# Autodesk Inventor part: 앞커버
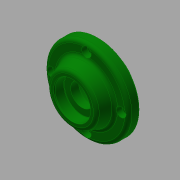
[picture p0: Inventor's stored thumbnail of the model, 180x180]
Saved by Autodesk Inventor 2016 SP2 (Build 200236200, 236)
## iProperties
Created: 2017-08
Part Number: 앞커버
Material: 알루미늄 6061
Document SubType Name: Modeling
Designer: mduedu
Density: 1 g/cm^3
Appearance: 진녹색
Author: mduedu
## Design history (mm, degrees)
sketch "스케치1"
  geometry: C1 r 35 at (0, 0); 1 further point
  constraints: 1 centre point, 1 coincident
  dimensions: "d0" = 70 diameter of C1
extrude "돌출1" new body sketch "스케치1" distance "d1" = 10; taper "d2" = 0 deg
sketch "스케치2"
  geometry: C1 r 24 at (0, 0); 1 further point
  constraints: 1 centre point, 1 coincident
  dimensions: "d3" = 48 diameter of C1
node "작업 평면1"
sketch "스케치3"
  geometry: C1 r 20 at (0, 0); 1 further point
  constraints: 1 centre point, 1 coincident
  dimensions: "d5" = 40 diameter of C1
feature "로프트1" sketch "스케치3" dims "d6" = 0, "d7" = 90 deg, "d8" = 0, "d9" = 90 deg
sketch "스케치4"
  geometry: C1 r 24 at (0, 0) reference; 1 further point
extrude "돌출2" join sketch "스케치4" distance "d10" = 8; taper "d11" = 0 deg
hole "구멍1" diameter "d14" = 40; stored, may be unused: countersink angle "d18" = 90 deg, drill point angle "d20" = 0 deg; dims "d12" = 10, "d13" = 10, "d15" = 6, "d16" = 4, "d17" = 2, "d19" = 12
hole "구멍2" diameter "d23" = 34; stored, may be unused: countersink angle "d27" = 90 deg, drill point angle "d29" = 0 deg; dims "d21" = 10, "d22" = 10, "d24" = 6, "d25" = 4, "d26" = 2, "d28" = 3
hole "구멍3" diameter "d32" = 19; stored, may be unused: countersink angle "d36" = 90 deg, drill point angle "d38" = 0 deg; dims "d30" = 10, "d31" = 10, "d33" = 6, "d34" = 4, "d35" = 2, "d37" = 3
chamfer "모따기1" distance "d39" = 1; stored, may be unused: second distance "d40" = 2, angle "d41" = 45 deg
sketch "스케치5"
  geometry: C1 r 15 at (0, 0); 1 further point
  constraints: 1 centre point, 1 coincident
  dimensions: "d42" = 30 diameter of C1
extrude "돌출3" cut sketch "스케치5" distance "d43" = 8.3; taper "d44" = 0 deg
chamfer "모따기2" distance "d47" = 0.8; stored, may be unused: second distance "d48" = 2, angle "d49" = 30 deg
fillet "모깎기1" dims "d50" = 0.3
fillet "모깎기2" dims "d51" = 0.3
fillet "모깎기3" dims "d52" = 3
sketch "스케치6" dims "d53" = 58
  geometry: 6 further points
  constraints: 2 vertical alignment, 1 coincident, 7 other
  dimensions: "d56" = 360 deg dimension on point (0, 0) point (0, 29) (derived)
sketch "스케치9"
  geometry: 4 further points
  constraints: 4 other
hole "구멍6" sketch "스케치9" at (-29, 0), (0, -29), (29, 0), (0, 29) diameter "d72" = 4.5; stored, may be unused: countersink angle "d76" = 90 deg, drill point angle "d78" = 0 deg; dims "d73" = 6, "d74" = 8, "d75" = 4.6, "d77" = 8
fillet "모깎기4" dims "d79" = 3
fillet "모깎기5" dims "d80" = 3
fillet "모깎기6" dims "d81" = 3
chamfer "모따기3" distance "d82" = 1; stored, may be unused: second distance "d83" = 2, angle "d84" = 30 deg
node "솔리드1"
other parameters: "d4" = 12
